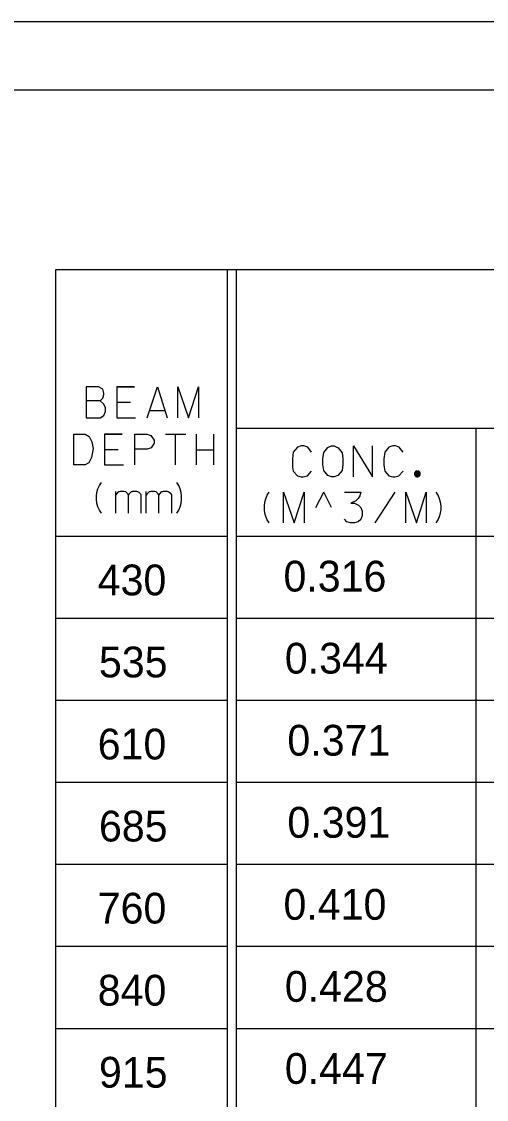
# Model space of a CAD drawing. Extents: x 635698 to 639877, y 296617 to 300175.
# Drawn here: x 636615 to 636660.4, y 299944.7 to 300049.8 of the extents above; entities that cross this region are included whole.
import ezdxf

# ---------------------------------------------------------------- set-up
doc = ezdxf.new("R2010")
doc.units = 0
doc.layers.add('2', color=7, linetype='Continuous')

msp = doc.modelspace()

# ---------------------------------------------------------------- linework, layer by layer
at = {"layer": '2'}
for p, q in [((636545.45, 300049.76), (637331.45, 300049.76)), ((637053.06, 300043.07), (636556.08, 300043.07)), ((636618.31, 300025.57), (636618.31, 299954.07)), ((636618.31, 300025.57), (636618.31, 299839.66)), ((637001.69, 300025.57), (636618.31, 300025.57)), ((636635.06, 300025.57), (636635.06, 299839.66)), ((636635.94, 300025.57), (636635.94, 299839.66)), ((636818.44, 300010.07), (636635.94, 300010.07)), ((636659.31, 300010.07), (636659.31, 299887.57)), ((636643.73, 300002.38), (636644.48, 300003.88)), ((636645.23, 300002.38), (636644.48, 300003.88)), ((636635.06, 299999.57), (636618.31, 299999.57)), ((636818.44, 299999.57), (636635.94, 299999.57)), ((636635.06, 299991.57), (636618.31, 299991.57)), ((636818.44, 299991.57), (636635.94, 299991.57)), ((636635.06, 299983.57), (636618.31, 299983.57)), ((636818.44, 299983.57), (636635.94, 299983.57)), ((636635.06, 299975.57), (636618.31, 299975.57)), ((636818.44, 299975.57), (636635.94, 299975.57)), ((636635.06, 299967.57), (636618.31, 299967.57)), ((636818.44, 299967.57), (636635.94, 299967.57)), ((636618.31, 299961.69), (636618.31, 299879.57)), ((636635.06, 299959.57), (636618.31, 299959.57)), ((636818.44, 299959.57), (636635.94, 299959.57)), ((636635.06, 299951.57), (636618.31, 299951.57)), ((636818.44, 299951.57), (636635.94, 299951.57))]:
    msp.add_line(p, q, dxfattribs=at)
for points in [[(636622.67, 300012.77), (636622.93, 300013.05), (636623.04, 300013.41), (636623.04, 300013.53), (636622.93, 300013.93), (636622.52, 300014.14), (636621.32, 300014.14), (636621.32, 300011.14), (636622.67, 300011.14), (636623.04, 300011.35), (636623.19, 300011.75), (636623.19, 300012.11), (636623.04, 300012.46), (636622.67, 300012.77), (636621.32, 300012.77)], [(636626.02, 300014.14), (636624.3, 300014.14), (636624.3, 300011.14), (636626.14, 300011.14)], [(636624.3, 300014.14), (636626.02, 300014.14)], [(636627.27, 300011.14), (636628.26, 300014.14), (636629.23, 300011.14)], [(636630.25, 300011.14), (636630.25, 300014.14), (636631.29, 300011.14), (636632.26, 300014.14), (636632.26, 300011.14)], [(636624.3, 300012.65), (636625.65, 300012.65)], [(636624.3, 300012.65), (636625.65, 300012.65)], [(636627.51, 300011.85), (636629, 300011.85)], [(636620.12, 300009.53), (636621.21, 300009.53), (636621.61, 300009.32), (636621.87, 300008.8), (636621.99, 300008.12), (636621.84, 300007.27), (636621.58, 300006.75), (636621.21, 300006.53), (636620.12, 300006.53), (636620.12, 300009.53)], [(636624.82, 300009.53), (636623.1, 300009.53), (636623.1, 300006.53), (636624.94, 300006.53)], [(636623.1, 300009.53), (636624.82, 300009.53)], [(636626.07, 300006.53), (636626.07, 300009.53), (636627.28, 300009.53), (636627.63, 300009.41), (636627.94, 300008.94), (636627.94, 300008.66), (636627.66, 300008.19), (636627.28, 300008.07), (636626.07, 300008.07)], [(636629.05, 300009.53), (636631.03, 300009.53)], [(636630.04, 300006.53), (636630.04, 300009.53)], [(636630.04, 300006.53), (636630.04, 300009.53)], [(636632.03, 300009.53), (636632.03, 300006.53)], [(636633.73, 300009.53), (636633.73, 300006.53)], [(636623.1, 300008.04), (636624.45, 300008.04)], [(636623.1, 300008.04), (636624.45, 300008.04)], [(636632.03, 300008.02), (636633.73, 300008.02)], [(636643.29, 300007.78), (636642.92, 300008.28), (636642.54, 300008.38), (636642.28, 300008.38), (636641.92, 300008.28), (636641.52, 300007.78), (636641.43, 300007.12), (636641.43, 300006.77), (636641.43, 300006.53), (636641.45, 300006.32), (636641.52, 300005.94), (636641.92, 300005.47), (636642.28, 300005.38), (636642.49, 300005.38), (636642.89, 300005.47), (636643.29, 300005.94)], [(636645.25, 300008.38), (636645.49, 300008.38), (636645.89, 300008.21), (636646.27, 300007.71), (636646.36, 300007.12), (636646.36, 300006.58), (636646.27, 300005.99), (636645.87, 300005.49), (636645.49, 300005.38), (636645.25, 300005.38), (636644.9, 300005.49), (636644.5, 300005.99), (636644.4, 300006.58), (636644.4, 300007.12), (636644.5, 300007.74), (636644.9, 300008.23), (636645.25, 300008.38)], [(636647.38, 300005.38), (636647.38, 300008.38), (636649.25, 300005.38), (636649.25, 300008.38)], [(636652.22, 300007.78), (636651.85, 300008.28), (636651.47, 300008.38), (636651.21, 300008.38), (636650.85, 300008.28), (636650.45, 300007.78), (636650.36, 300007.12), (636650.36, 300006.77), (636650.36, 300006.53), (636650.38, 300006.32), (636650.45, 300005.94), (636650.85, 300005.47), (636651.21, 300005.38), (636651.42, 300005.38), (636651.82, 300005.47), (636652.22, 300005.94)], [(636653.9, 300005.66), (636653.9, 300005.69), (636653.9, 300005.72), (636653.89, 300005.75), (636653.88, 300005.78), (636653.87, 300005.8), (636653.85, 300005.83), (636653.83, 300005.85), (636653.81, 300005.87), (636653.79, 300005.89), (636653.76, 300005.91), (636653.73, 300005.92), (636653.71, 300005.93), (636653.68, 300005.94), (636653.65, 300005.94), (636653.62, 300005.95), (636653.59, 300005.94), (636653.56, 300005.94), (636653.53, 300005.93), (636653.5, 300005.92), (636653.48, 300005.91), (636653.45, 300005.89), (636653.43, 300005.87), (636653.41, 300005.85), (636653.39, 300005.83), (636653.37, 300005.8), (636653.36, 300005.78), (636653.35, 300005.75), (636653.34, 300005.72), (636653.34, 300005.69), (636653.33, 300005.66), (636653.34, 300005.63), (636653.34, 300005.6), (636653.35, 300005.57), (636653.36, 300005.54), (636653.37, 300005.52), (636653.39, 300005.49), (636653.41, 300005.47), (636653.43, 300005.45), (636653.45, 300005.43), (636653.48, 300005.41), (636653.5, 300005.4), (636653.53, 300005.39), (636653.56, 300005.38), (636653.59, 300005.38), (636653.62, 300005.38), (636653.65, 300005.38), (636653.68, 300005.38), (636653.71, 300005.39), (636653.73, 300005.4), (636653.76, 300005.41), (636653.79, 300005.43), (636653.81, 300005.45), (636653.83, 300005.47), (636653.85, 300005.49), (636653.87, 300005.52), (636653.88, 300005.54), (636653.89, 300005.57), (636653.9, 300005.6), (636653.9, 300005.63), (636653.9, 300005.66)], [(636653.84, 300005.66), (636653.84, 300005.68), (636653.84, 300005.71), (636653.83, 300005.73), (636653.82, 300005.75), (636653.81, 300005.77), (636653.8, 300005.79), (636653.79, 300005.81), (636653.77, 300005.83), (636653.75, 300005.84), (636653.73, 300005.86), (636653.71, 300005.87), (636653.69, 300005.87), (636653.67, 300005.88), (636653.64, 300005.88), (636653.62, 300005.89), (636653.6, 300005.88), (636653.57, 300005.88), (636653.55, 300005.87), (636653.53, 300005.87), (636653.51, 300005.86), (636653.49, 300005.84), (636653.47, 300005.83), (636653.45, 300005.81), (636653.44, 300005.79), (636653.42, 300005.77), (636653.41, 300005.75), (636653.4, 300005.73), (636653.4, 300005.71), (636653.4, 300005.68), (636653.39, 300005.66), (636653.4, 300005.64), (636653.4, 300005.61), (636653.4, 300005.59), (636653.41, 300005.57), (636653.42, 300005.55), (636653.44, 300005.53), (636653.45, 300005.51), (636653.47, 300005.49), (636653.49, 300005.48), (636653.51, 300005.47), (636653.53, 300005.45), (636653.55, 300005.45), (636653.57, 300005.44), (636653.6, 300005.44), (636653.62, 300005.43), (636653.64, 300005.44), (636653.67, 300005.44), (636653.69, 300005.45), (636653.71, 300005.45), (636653.73, 300005.47), (636653.75, 300005.48), (636653.77, 300005.49), (636653.79, 300005.51), (636653.8, 300005.53), (636653.81, 300005.55), (636653.82, 300005.57), (636653.83, 300005.59), (636653.84, 300005.61), (636653.84, 300005.64), (636653.84, 300005.66)], [(636653.78, 300005.66), (636653.78, 300005.68), (636653.78, 300005.69), (636653.78, 300005.71), (636653.77, 300005.73), (636653.76, 300005.74), (636653.75, 300005.76), (636653.74, 300005.77), (636653.73, 300005.78), (636653.72, 300005.79), (636653.7, 300005.8), (636653.69, 300005.81), (636653.67, 300005.82), (636653.65, 300005.82), (636653.64, 300005.82), (636653.62, 300005.82), (636653.6, 300005.82), (636653.58, 300005.82), (636653.57, 300005.82), (636653.55, 300005.81), (636653.54, 300005.8), (636653.52, 300005.79), (636653.51, 300005.78), (636653.5, 300005.77), (636653.49, 300005.76), (636653.48, 300005.74), (636653.47, 300005.73), (636653.46, 300005.71), (636653.46, 300005.69), (636653.46, 300005.68), (636653.45, 300005.66), (636653.46, 300005.64), (636653.46, 300005.63), (636653.46, 300005.61), (636653.47, 300005.59), (636653.48, 300005.58), (636653.49, 300005.56), (636653.5, 300005.55), (636653.51, 300005.54), (636653.52, 300005.53), (636653.54, 300005.52), (636653.55, 300005.51), (636653.57, 300005.5), (636653.58, 300005.5), (636653.6, 300005.5), (636653.62, 300005.5), (636653.64, 300005.5), (636653.65, 300005.5), (636653.67, 300005.5), (636653.69, 300005.51), (636653.7, 300005.52), (636653.72, 300005.53), (636653.73, 300005.54), (636653.74, 300005.55), (636653.75, 300005.56), (636653.76, 300005.58), (636653.77, 300005.59), (636653.78, 300005.61), (636653.78, 300005.63), (636653.78, 300005.64), (636653.78, 300005.66)], [(636653.72, 300005.66), (636653.72, 300005.67), (636653.72, 300005.68), (636653.72, 300005.69), (636653.72, 300005.7), (636653.71, 300005.71), (636653.7, 300005.72), (636653.7, 300005.73), (636653.69, 300005.74), (636653.68, 300005.75), (636653.67, 300005.75), (636653.66, 300005.76), (636653.65, 300005.76), (636653.64, 300005.76), (636653.63, 300005.76), (636653.62, 300005.76), (636653.61, 300005.76), (636653.6, 300005.76), (636653.59, 300005.76), (636653.58, 300005.76), (636653.57, 300005.75), (636653.56, 300005.75), (636653.55, 300005.74), (636653.54, 300005.73), (636653.53, 300005.72), (636653.53, 300005.71), (636653.52, 300005.7), (636653.52, 300005.69), (636653.52, 300005.68), (636653.51, 300005.67), (636653.51, 300005.66), (636653.51, 300005.65), (636653.52, 300005.64), (636653.52, 300005.63), (636653.52, 300005.62), (636653.53, 300005.61), (636653.53, 300005.6), (636653.54, 300005.59), (636653.55, 300005.58), (636653.56, 300005.58), (636653.57, 300005.57), (636653.58, 300005.56), (636653.59, 300005.56), (636653.6, 300005.56), (636653.61, 300005.56), (636653.62, 300005.56), (636653.63, 300005.56), (636653.64, 300005.56), (636653.65, 300005.56), (636653.66, 300005.56), (636653.67, 300005.57), (636653.68, 300005.58), (636653.69, 300005.58), (636653.7, 300005.59), (636653.7, 300005.6), (636653.71, 300005.61), (636653.72, 300005.62), (636653.72, 300005.63), (636653.72, 300005.64), (636653.72, 300005.65), (636653.72, 300005.66)], [(636653.66, 300005.66), (636653.66, 300005.66), (636653.66, 300005.67), (636653.66, 300005.67), (636653.66, 300005.68), (636653.66, 300005.68), (636653.66, 300005.69), (636653.65, 300005.69), (636653.65, 300005.69), (636653.65, 300005.7), (636653.64, 300005.7), (636653.64, 300005.7), (636653.63, 300005.7), (636653.63, 300005.7), (636653.62, 300005.7), (636653.62, 300005.71), (636653.61, 300005.7), (636653.61, 300005.7), (636653.61, 300005.7), (636653.6, 300005.7), (636653.6, 300005.7), (636653.59, 300005.7), (636653.59, 300005.69), (636653.59, 300005.69), (636653.58, 300005.69), (636653.58, 300005.68), (636653.58, 300005.68), (636653.58, 300005.67), (636653.58, 300005.67), (636653.57, 300005.66), (636653.57, 300005.66), (636653.57, 300005.66), (636653.58, 300005.65), (636653.58, 300005.65), (636653.58, 300005.64), (636653.58, 300005.64), (636653.58, 300005.63), (636653.59, 300005.63), (636653.59, 300005.63), (636653.59, 300005.62), (636653.6, 300005.62), (636653.6, 300005.62), (636653.61, 300005.62), (636653.61, 300005.62), (636653.61, 300005.62), (636653.62, 300005.62), (636653.62, 300005.62), (636653.63, 300005.62), (636653.63, 300005.62), (636653.64, 300005.62), (636653.64, 300005.62), (636653.65, 300005.62), (636653.65, 300005.63), (636653.65, 300005.63), (636653.66, 300005.63), (636653.66, 300005.64), (636653.66, 300005.64), (636653.66, 300005.65), (636653.66, 300005.65), (636653.66, 300005.66), (636653.66, 300005.66)], [(636622.8, 300001.82), (636622.61, 300002.13), (636622.46, 300002.46), (636622.37, 300002.79), (636622.32, 300003.15), (636622.32, 300003.5), (636622.37, 300003.86), (636622.46, 300004.19), (636622.61, 300004.52), (636622.8, 300004.82)], [(636630.15, 300001.82), (636630.34, 300002.13), (636630.48, 300002.46), (636630.58, 300002.79), (636630.62, 300003.15), (636630.62, 300003.5), (636630.58, 300003.86), (636630.48, 300004.19), (636630.34, 300004.52), (636630.15, 300004.82)], [(636624.2, 300003.57), (636624.25, 300003.62), (636624.29, 300003.71), (636624.51, 300003.93), (636624.58, 300003.95), (636624.67, 300003.97), (636625, 300003.97), (636625.14, 300003.93), (636625.24, 300003.86), (636625.33, 300003.76), (636625.4, 300003.6), (636625.43, 300003.55), (636625.47, 300003.62), (636625.52, 300003.71), (636625.73, 300003.93), (636625.8, 300003.95), (636625.88, 300003.97), (636626.23, 300003.97), (636626.32, 300003.93), (636626.44, 300003.88), (636626.56, 300003.78), (636626.61, 300003.71), (636626.65, 300003.62), (636626.65, 300001.82)], [(636624.2, 300001.82), (636624.2, 300003.95)], [(636625.43, 300001.82), (636625.43, 300003.57)], [(636627.17, 300003.57), (636627.22, 300003.62), (636627.27, 300003.71), (636627.48, 300003.93), (636627.55, 300003.95), (636627.65, 300003.97), (636627.98, 300003.97), (636628.12, 300003.93), (636628.21, 300003.86), (636628.31, 300003.76), (636628.38, 300003.6), (636628.4, 300003.55), (636628.45, 300003.62), (636628.5, 300003.71), (636628.71, 300003.93), (636628.78, 300003.95), (636628.85, 300003.97), (636629.21, 300003.97), (636629.3, 300003.93), (636629.42, 300003.88), (636629.54, 300003.78), (636629.58, 300003.71), (636629.63, 300003.62), (636629.63, 300001.82)], [(636627.17, 300001.82), (636627.17, 300003.95)], [(636628.4, 300001.82), (636628.4, 300003.57)], [(636639.17, 300000.88), (636638.98, 300001.18), (636638.84, 300001.51), (636638.74, 300001.84), (636638.7, 300002.2), (636638.7, 300002.55), (636638.74, 300002.91), (636638.84, 300003.24), (636638.98, 300003.57), (636639.17, 300003.88)], [(636640.57, 300000.88), (636640.57, 300003.88), (636641.61, 300000.88), (636642.58, 300003.88), (636642.58, 300000.88)], [(636646.52, 300003.88), (636648.11, 300003.88), (636648.01, 300003.52), (636647.85, 300003.26), (636647.61, 300003.02), (636647.14, 300002.79), (636647.49, 300002.79), (636647.87, 300002.62), (636648.11, 300002.39), (636648.22, 300002.01), (636648.22, 300001.61), (636648.11, 300001.21), (636647.85, 300000.97), (636647.49, 300000.88), (636647.09, 300000.88), (636646.74, 300000.97), (636646.52, 300001.23)], [(636649.5, 300000.88), (636651.46, 300003.88)], [(636652.48, 300000.88), (636652.48, 300003.88), (636653.52, 300000.88), (636654.49, 300003.88), (636654.49, 300000.88)], [(636655.45, 300000.88), (636655.64, 300001.18), (636655.78, 300001.51), (636655.88, 300001.84), (636655.93, 300002.2), (636655.93, 300002.55), (636655.88, 300002.91), (636655.78, 300003.24), (636655.64, 300003.57), (636655.45, 300003.88)]]:
    msp.add_lwpolyline(points, dxfattribs=at)

# ---------------------------------------------------------------- texts
for s, p in [('0.316', (636640.56, 299994.19)), ('430', (636622.44, 299993.82)), ('535', (636622.56, 299985.82)), ('0.344', (636640.69, 299986.19)), ('610', (636622.44, 299977.82)), ('0.371', (636640.94, 299978.19)), ('0.391', (636640.94, 299970.19)), ('685', (636622.56, 299969.82)), ('760', (636622.44, 299961.82)), ('0.410', (636640.56, 299962.19)), ('0.428', (636640.69, 299954.19)), ('840', (636622.44, 299953.82)), ('915', (636622.56, 299945.82)), ('0.447', (636640.69, 299946.19))]:
    msp.add_text(s, height=3, dxfattribs=at).set_placement(p)

doc.saveas('drawing.dxf')
